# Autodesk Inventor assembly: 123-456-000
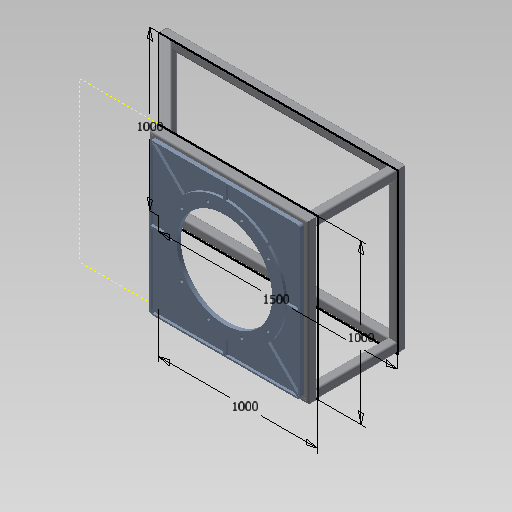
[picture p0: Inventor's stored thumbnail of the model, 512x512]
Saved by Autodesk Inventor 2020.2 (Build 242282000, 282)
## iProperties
Created: 2006-08
Part Number: 123-456-000
Document SubType Name: Konstrukcja spawana
Designer: F.Stasiak
Description: Podstawa
Weld Material: Spawana stal miękka
Mass: 178274 g
Surface Area: 59444.6 cm^2
Volume: 22710 cm^3
Density: 7.85 g/cm^3
Manager: www.cadconsulting.pl
Company: Fabian Stasiak CAD Consulting
Author: F.Stasiak
Subject: Zbiór ćwiczeń. Autodesk Inventor 2020. Kurs podstawowy
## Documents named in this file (15)
- C:\2020_Kurs_podstawowy\R6 Zespoły\BOM\123-456-000.iam
- C:\2020_Kurs_podstawowy\R6 Zespoły\BOM\Szkielet podstawy.ipt
- C:\2020_Kurs_podstawowy\R6 Zespoły\BOM\123-456-013.ipt
- C:\2020_Kurs_podstawowy\R6 Zespoły\BOM\Podstawa_0001\SQ 60x6_Spód_1.ipt
- C:\2020_Kurs_podstawowy\R6 Zespoły\BOM\Podstawa_0001\SQ 60x6_Spód_2.ipt
- C:\2020_Kurs_podstawowy\R6 Zespoły\BOM\Podstawa_0001\SQ 60x6_Spód_3.ipt
- C:\2020_Kurs_podstawowy\R6 Zespoły\BOM\Podstawa_0001\SQ 60x6_Spód_4.ipt
- C:\2020_Kurs_podstawowy\R6 Zespoły\BOM\Podstawa_0001\SQ 60x6_Góra_1.ipt
- C:\2020_Kurs_podstawowy\R6 Zespoły\BOM\Podstawa_0001\SQ 60x6_Góra_2.ipt
- C:\2020_Kurs_podstawowy\R6 Zespoły\BOM\Podstawa_0001\SQ 60x6_Góra_3.ipt
- C:\2020_Kurs_podstawowy\R6 Zespoły\BOM\Podstawa_0001\SQ 60x6_Góra_4.ipt
- C:\2020_Kurs_podstawowy\R6 Zespoły\BOM\Podstawa_0001\SQ 60x6_Bok_1.ipt
- C:\2020_Kurs_podstawowy\R6 Zespoły\BOM\Podstawa_0001\SQ 60x6_Bok_2.ipt
- C:\2020_Kurs_podstawowy\R6 Zespoły\BOM\Podstawa_0001\SQ 60x6_Bok_3.ipt
- C:\2020_Kurs_podstawowy\R6 Zespoły\BOM\Podstawa_0001\SQ 60x6_Bok_4.ipt
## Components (14 placed, 14 different names)
1. Szkielet podstawy:1
2. 123-456-013:1 — Równoległy:2, Zestawiający:1
3. SQ 60x6_Spód_1:1
4. SQ 60x6_Spód_2:1
5. SQ 60x6_Spód_3:1
6. SQ 60x6_Spód_4:1
7. SQ 60x6_Góra_1:1
8. SQ 60x6_Góra_2:1 — Zestawiający:1
9. SQ 60x6_Góra_3:1 — Równoległy:2
10. SQ 60x6_Góra_4:1
11. SQ 60x6_Bok_1:1
12. SQ 60x6_Bok_2:1
13. SQ 60x6_Bok_3:1
14. SQ 60x6_Bok_4:1
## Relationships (2: Flush 1, Mate 1)
- Równoległy:2 [Flush]: 123-456-013:1 ↔ SQ 60x6_Góra_3:1
- Zestawiający:1 [Mate]: 123-456-013:1 ↔ SQ 60x6_Góra_2:1
